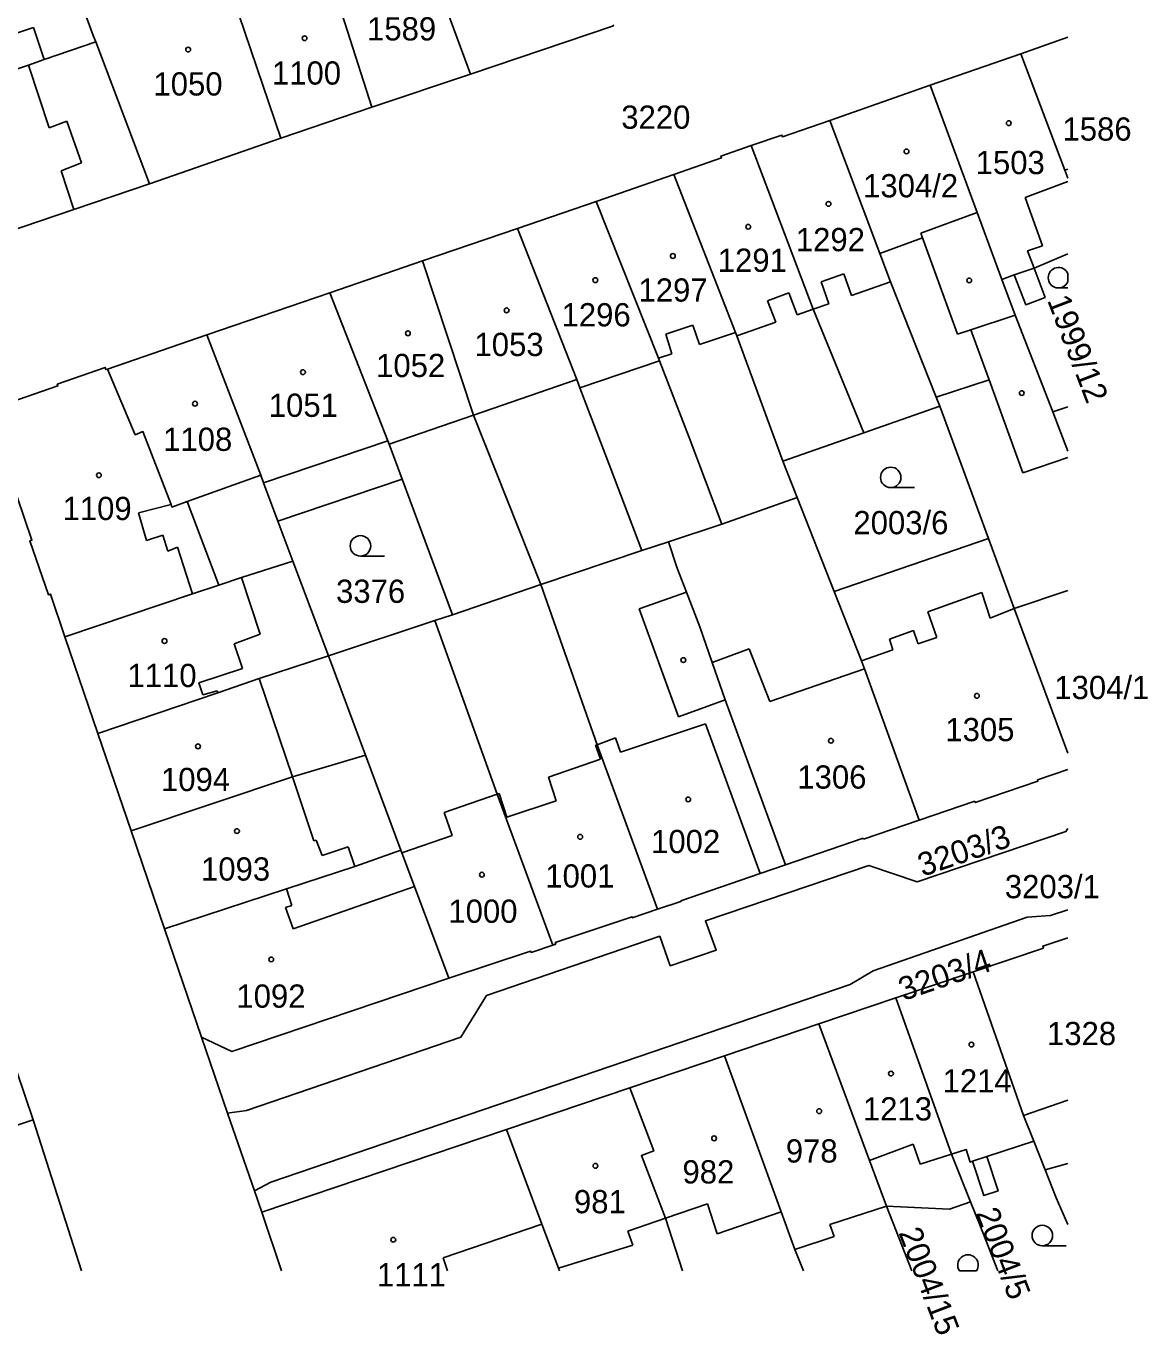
# Model space of a CAD drawing. Extents: x -564952 to -564307, y -1202373 to -1201847.
# Drawn here: x -564390.9 to -564308.8, y -1202366.4 to -1202270.6 of the extents above; entities that cross this region are included whole.
import ezdxf

# ---------------------------------------------------------------- set-up
doc = ezdxf.new("R2010")
doc.units = 0
for name, color, linetype in [('Hranice parcel', 7, 'Continuous'), ('Parcelní čísla', 7, 'Continuous'), ('Vnitřní kresba', 7, 'Continuous'), ('Značky budov', 7, 'Continuous'), ('Značky kultur', 7, 'Continuous')]:
    doc.layers.add(name, color=color, linetype=linetype)

msp = doc.modelspace()

# ---------------------------------------------------------------- linework, layer by layer
at = {"layer": 'Hranice parcel'}
for p, q in [((-564372.23, -1202278.84), (-564376.25, -1202266.98)), ((-564368.89, -1202266.13), (-564365.56, -1202276.57)), ((-564385.77, -1202271.77), (-564385.95, -1202271.31)), ((-564381.83, -1202282.18), (-564385.77, -1202271.77)), ((-564314.648, -1202271.429), (-564318.08, -1202272.65)), ((-564324.71, -1202274.95), (-564318.08, -1202272.65)), ((-564401.02, -1202276.91), (-564390.69, -1202273.49)), ((-564365.56, -1202276.57), (-564358.34, -1202274.15)), ((-564332.06, -1202277.53), (-564324.71, -1202274.95)), ((-564321.28, -1202284.27), (-564324.71, -1202274.95)), ((-564365.56, -1202276.57), (-564372.23, -1202278.84)), ((-564372.23, -1202278.84), (-564381.83, -1202282.18)), ((-564343.48, -1202281.48), (-564349.16, -1202283.47)), ((-564349.16, -1202283.47), (-564354.92, -1202285.44)), ((-564319.47, -1202289.16), (-564321.28, -1202284.27)), ((-564361.86, -1202287.81), (-564354.92, -1202285.44)), ((-564368.65, -1202290.15), (-564361.86, -1202287.81)), ((-564319.47, -1202289.16), (-564318.5, -1202291.78)), ((-564368.65, -1202290.15), (-564377.64, -1202293.21)), ((-564318.5, -1202291.78), (-564315.75, -1202298.85)), ((-564384.92, -1202295.72), (-564377.64, -1202293.21)), ((-564329.57, -1202300.38), (-564324.01, -1202298.43)), ((-564324.01, -1202298.43), (-564324.27, -1202297.77)), ((-564320.44, -1202308.13), (-564324.01, -1202298.43)), ((-564315.75, -1202298.85), (-564314.648, -1202298.478)), ((-564335.5, -1202302.46), (-564329.57, -1202300.38)), ((-564363.34, -1202303.78), (-564364.29, -1202301.23)), ((-564334.45, -1202305.13), (-564335.5, -1202302.46)), ((-564373.49, -1202304.05), (-564372.44, -1202306.86)), ((-564372.44, -1202306.86), (-564363.34, -1202303.78)), ((-564359.66, -1202313.7), (-564363.34, -1202303.78)), ((-564339.97, -1202307.06), (-564334.45, -1202305.13)), ((-564334.45, -1202305.13), (-564331.73, -1202312.01)), ((-564372.44, -1202306.86), (-564371.35, -1202309.77)), ((-564343.86, -1202308.36), (-564339.97, -1202307.06)), ((-564331.73, -1202312.01), (-564320.44, -1202308.13)), ((-564320.44, -1202308.13), (-564318.56, -1202313.24)), ((-564345.81, -1202309.01), (-564353.2, -1202311.48)), ((-564345.81, -1202309.01), (-564343.86, -1202308.36)), ((-564371.35, -1202309.77), (-564375.1, -1202310.97)), ((-564368.75, -1202316.71), (-564371.35, -1202309.77)), ((-564375.1, -1202310.97), (-564376.76, -1202311.53)), ((-564353.2, -1202311.48), (-564359.66, -1202313.7)), ((-564331.73, -1202312.01), (-564329.74, -1202317.06)), ((-564359.66, -1202313.7), (-564360.97, -1202314.13)), ((-564318.56, -1202313.24), (-564314.648, -1202323.815)), ((-564360.97, -1202314.13), (-564368.75, -1202316.71)), ((-564388.02, -1202315.32), (-564385.61, -1202322.39)), ((-564368.75, -1202316.71), (-564373.8, -1202318.37)), ((-564368.75, -1202316.71), (-564366.03, -1202323.98)), ((-564385.61, -1202322.39), (-564383.18, -1202329.52)), ((-564366.03, -1202323.98), (-564363.44, -1202330.93)), ((-564329.6, -1202330.13), (-564325.52, -1202328.74)), ((-564383.18, -1202329.52), (-564380.74, -1202336.69)), ((-564335.31, -1202332), (-564329.62, -1202330.05)), ((-564329.62, -1202330.05), (-564329.6, -1202330.13)), ((-564363.44, -1202330.93), (-564366.81, -1202332.11)), ((-564363.44, -1202330.93), (-564363.37, -1202331.12)), ((-564380.74, -1202336.69), (-564378.04, -1202344.61)), ((-564327.23, -1202341.74), (-564321.57, -1202339.83)), ((-564317.9, -1202350.33), (-564321.57, -1202339.83)), ((-564327.23, -1202341.74), (-564332.87, -1202343.64)), ((-564323.16, -1202353.16), (-564327.23, -1202341.74)), ((-564332.87, -1202343.64), (-564339.77, -1202345.98)), ((-564376.12, -1202350.17), (-564378.04, -1202344.61)), ((-564339.77, -1202345.98), (-564346.68, -1202348.31)), ((-564346.68, -1202348.31), (-564355.71, -1202351.36)), ((-564376.12, -1202350.17), (-564374.16, -1202355.86)), ((-564386.818, -1202361.698), (-564390.35, -1202350.66)), ((-564317.14, -1202352.21), (-564317.9, -1202350.33)), ((-564355.71, -1202351.36), (-564373.62, -1202357.41)), ((-564316.3, -1202354.32), (-564317.14, -1202352.21)), ((-564323.16, -1202353.16), (-564321.77, -1202356.66)), ((-564314.648, -1202353.848), (-564316.3, -1202354.32)), ((-564316.3, -1202354.32), (-564315.49, -1202356.35)), ((-564373.62, -1202357.41), (-564374.16, -1202355.86)), ((-564326.071, -1202361.698), (-564327.92, -1202356.96)), ((-564315.49, -1202356.35), (-564314.648, -1202358.316)), ((-564373.62, -1202357.41), (-564372.175, -1202361.698))]:
    msp.add_line(p, q, dxfattribs=at)
for points in [[(-564358.34, -1202274.15), (-564362.08, -1202264.03), (-564362.9, -1202261.82)], [(-564385.95, -1202271.31), (-564386.4, -1202270.12), (-564386.53, -1202269.77), (-564387.18, -1202268.03)], [(-564358.34, -1202274.15), (-564347.89, -1202270.6), (-564347.92, -1202270.53)], [(-564390.69, -1202273.49), (-564389.53, -1202273.08), (-564385.77, -1202271.77)], [(-564318.08, -1202272.65), (-564314.87, -1202281.17), (-564314.648, -1202281.763)], [(-564332.06, -1202277.53), (-564335.53, -1202278.73), (-564335.57, -1202278.6), (-564337.81, -1202279.37)], [(-564324.27, -1202297.77), (-564327.62, -1202289.35), (-564328.4, -1202287.27), (-564332.06, -1202277.53)], [(-564337.81, -1202279.37), (-564340.03, -1202280.14), (-564339.99, -1202280.27), (-564343.48, -1202281.48)], [(-564329.57, -1202300.38), (-564333.29, -1202291.34), (-564337.81, -1202279.37)], [(-564397.45, -1202287.47), (-564387.37, -1202284.06), (-564381.83, -1202282.18)], [(-564343.48, -1202281.48), (-564338.97, -1202293.04), (-564338.87, -1202293.3), (-564335.5, -1202302.46)], [(-564339.97, -1202307.06), (-564342.36, -1202300.74), (-564344.53, -1202295.11), (-564344.6, -1202294.93), (-564349.16, -1202283.47)], [(-564354.92, -1202285.44), (-564350.58, -1202296.49), (-564350.35, -1202297.09), (-564348.07, -1202303.02), (-564345.81, -1202309.01)], [(-564353.2, -1202311.48), (-564358.13, -1202299.1), (-564361.86, -1202287.81)], [(-564314.648, -1202287.303), (-564317.11, -1202288.33), (-564316.3, -1202290.48)], [(-564316.3, -1202290.48), (-564317.73, -1202291.02), (-564318.56, -1202288.82), (-564319.47, -1202289.16)], [(-564364.29, -1202301.23), (-564364.39, -1202300.97), (-564368.65, -1202290.15)], [(-564318.5, -1202291.78), (-564321.74, -1202292.86), (-564320.41, -1202296.51), (-564324.27, -1202297.77)], [(-564377.64, -1202293.21), (-564373.7, -1202303.49), (-564373.49, -1202304.05)], [(-564393.68, -1202298.73), (-564388.54, -1202296.96), (-564388.58, -1202296.83), (-564385.09, -1202295.6), (-564385.03, -1202295.76), (-564384.92, -1202295.72)], [(-564384.92, -1202295.72), (-564382.88, -1202300.53), (-564382.32, -1202300.3), (-564380.25, -1202305.63), (-564380.19, -1202305.82), (-564379.07, -1202305.42), (-564376.76, -1202311.53)], [(-564388.02, -1202315.32), (-564389.09, -1202312.19), (-564389.23, -1202312.24), (-564390.58, -1202308.29), (-564390.44, -1202308.24), (-564393.68, -1202298.73)], [(-564315.75, -1202298.85), (-564314.648, -1202301.72)], [(-564341.56, -1202314.59), (-564342.54, -1202312.05), (-564343.22, -1202310.3), (-564343.86, -1202308.36)], [(-564376.76, -1202311.53), (-564378.7, -1202312.18), (-564388.02, -1202315.32)], [(-564344.67, -1202335.25), (-564349.09, -1202323.21), (-564353.2, -1202311.48)], [(-564352.33, -1202337.87), (-564356.4, -1202326.83), (-564360.97, -1202314.13)], [(-564335.31, -1202332), (-564339.71, -1202319.93), (-564340.66, -1202317.19), (-564341.56, -1202314.59)], [(-564329.74, -1202317.06), (-564329.53, -1202317.65), (-564325.52, -1202328.74)], [(-564373.8, -1202318.37), (-564376.83, -1202319.4), (-564385.61, -1202322.39)], [(-564366.03, -1202323.98), (-564371.38, -1202325.57), (-564383.18, -1202329.52)], [(-564325.52, -1202328.74), (-564321.45, -1202327.35), (-564321.42, -1202327.44), (-564316.83, -1202325.88), (-564316.86, -1202325.78), (-564314.648, -1202325.026)], [(-564314.648, -1202329.344), (-564314.78, -1202329.56), (-564325.67, -1202333.25), (-564329.21, -1202332.05), (-564341.16, -1202336.1), (-564340.37, -1202338.24), (-564343.73, -1202339.38), (-564344.5, -1202337.22), (-564357.19, -1202341.56), (-564359.05, -1202344.6), (-564374.74, -1202349.96), (-564376.12, -1202350.17)], [(-564363.37, -1202331.12), (-564362.45, -1202333.57), (-564359.93, -1202340.28)], [(-564366.81, -1202332.11), (-564371.82, -1202333.76), (-564380.74, -1202336.69)], [(-564342.97, -1202334.62), (-564337.16, -1202332.63), (-564335.31, -1202332)], [(-564344.67, -1202335.25), (-564342.95, -1202334.69), (-564342.97, -1202334.62)], [(-564374.16, -1202355.86), (-564372.96, -1202355.22), (-564330.58, -1202340.76), (-564328.9, -1202339.76), (-564317.61, -1202335.83), (-564315.91, -1202335.71), (-564314.648, -1202335.286)], [(-564352.33, -1202337.87), (-564352.11, -1202337.79), (-564352.15, -1202337.68), (-564346.53, -1202335.8), (-564346.51, -1202335.87), (-564344.67, -1202335.25)], [(-564390.35, -1202350.66), (-564392.14, -1202345.32), (-564392.29, -1202345.37), (-564395.36, -1202336.41)], [(-564359.93, -1202340.28), (-564353.95, -1202338.32), (-564353.92, -1202338.41), (-564352.33, -1202337.87)], [(-564321.57, -1202339.83), (-564316.43, -1202338.09), (-564316.48, -1202337.95), (-564314.648, -1202337.328)], [(-564378.04, -1202344.61), (-564375.81, -1202345.65), (-564359.93, -1202340.28)], [(-564327.92, -1202356.96), (-564329.16, -1202353.63), (-564332.87, -1202343.64)], [(-564339.77, -1202345.98), (-564335.62, -1202357.39), (-564334.61, -1202360.15)], [(-564342.842, -1202361.698), (-564344.09, -1202357.85), (-564345.84, -1202353.27), (-564344.94, -1202352.93), (-564346.68, -1202348.31)], [(-564390.35, -1202350.66), (-564395.73, -1202352.45), (-564395.78, -1202352.31), (-564402.54, -1202354.66), (-564406.74, -1202356.11)], [(-564355.71, -1202351.36), (-564353.14, -1202358.28), (-564351.92, -1202361.5), (-564351.846, -1202361.698)], [(-564317.14, -1202352.21), (-564320.58, -1202353.34), (-564319.75, -1202355.86), (-564320.79, -1202356.2), (-564321.62, -1202353.68), (-564321.8, -1202353.74), (-564322.09, -1202352.82), (-564323.16, -1202353.16)], [(-564327.92, -1202356.96), (-564323.31, -1202357.18), (-564321.77, -1202356.66)], [(-564321.77, -1202356.66), (-564321.08, -1202358.34), (-564319.76, -1202361.698)], [(-564334.61, -1202360.15), (-564333.994, -1202361.698)]]:
    msp.add_lwpolyline(points, dxfattribs=at)
at = {"layer": 'Vnitřní kresba'}
for p, q in [((-564390.31, -1202270.74), (-564393.18, -1202271.69)), ((-564389.53, -1202273.08), (-564390.31, -1202270.74)), ((-564389.18, -1202278.07), (-564390.69, -1202273.49)), ((-564387.89, -1202277.58), (-564389.18, -1202278.07)), ((-564386.81, -1202280.64), (-564387.89, -1202277.58)), ((-564388.31, -1202281.21), (-564386.81, -1202280.64)), ((-564387.37, -1202284.06), (-564388.31, -1202281.21)), ((-564314.87, -1202281.17), (-564314.648, -1202281.087)), ((-564317.77, -1202283.18), (-564314.648, -1202281.999)), ((-564316.49, -1202286.71), (-564317.77, -1202283.18)), ((-564325.41, -1202285.79), (-564321.28, -1202284.27)), ((-564328.4, -1202287.27), (-564325.29, -1202286.12)), ((-564325.29, -1202286.12), (-564325.41, -1202285.79)), ((-564322.72, -1202293.18), (-564325.29, -1202286.12)), ((-564317.59, -1202287.07), (-564316.49, -1202286.71)), ((-564317.11, -1202288.33), (-564317.59, -1202287.07)), ((-564332.7, -1202289.33), (-564331.04, -1202288.75)), ((-564331.04, -1202288.75), (-564330.48, -1202290.35)), ((-564318.56, -1202288.82), (-564317.11, -1202288.33)), ((-564332.14, -1202290.94), (-564332.7, -1202289.33)), ((-564330.48, -1202290.35), (-564327.62, -1202289.35)), ((-564336.61, -1202290.74), (-564335.05, -1202290.15)), ((-564336.02, -1202292.3), (-564336.61, -1202290.74)), ((-564335.05, -1202290.15), (-564334.46, -1202291.75)), ((-564333.29, -1202291.34), (-564332.14, -1202290.94)), ((-564334.46, -1202291.75), (-564333.29, -1202291.34)), ((-564344.06, -1202293.18), (-564342.08, -1202292.51)), ((-564342.08, -1202292.51), (-564341.6, -1202293.92)), ((-564338.87, -1202293.3), (-564336.02, -1202292.3)), ((-564322.72, -1202293.18), (-564321.74, -1202292.86)), ((-564343.61, -1202294.6), (-564344.06, -1202293.18)), ((-564341.6, -1202293.92), (-564338.97, -1202293.04)), ((-564344.6, -1202294.93), (-564343.61, -1202294.6)), ((-564350.35, -1202297.09), (-564344.53, -1202295.11)), ((-564350.58, -1202296.49), (-564358.13, -1202299.1)), ((-564317.94, -1202303.31), (-564320.41, -1202296.51)), ((-564358.13, -1202299.1), (-564364.29, -1202301.23)), ((-564364.39, -1202300.97), (-564373.49, -1202304.05)), ((-564314.648, -1202302.184), (-564317.94, -1202303.31)), ((-564373.7, -1202303.49), (-564379.07, -1202305.42)), ((-564382.63, -1202306.23), (-564380.25, -1202305.63)), ((-564382.06, -1202308.26), (-564382.63, -1202306.23)), ((-564380.85, -1202307.88), (-564382.06, -1202308.26)), ((-564380.5, -1202309.05), (-564380.85, -1202307.88)), ((-564379.78, -1202308.76), (-564380.5, -1202309.05)), ((-564378.7, -1202312.18), (-564379.78, -1202308.76)), ((-564375.1, -1202310.97), (-564373.73, -1202315.12)), ((-564318.56, -1202313.24), (-564314.648, -1202311.917)), ((-564346.02, -1202313.26), (-564342.54, -1202312.05)), ((-564320.94, -1202312.07), (-564324.9, -1202313.48)), ((-564320.34, -1202313.94), (-564320.94, -1202312.07)), ((-564343.12, -1202321.18), (-564346.02, -1202313.26)), ((-564324.24, -1202315.37), (-564324.9, -1202313.48)), ((-564318.56, -1202313.24), (-564320.34, -1202313.94)), ((-564325.93, -1202314.86), (-564327.7, -1202315.48)), ((-564325.68, -1202315.64), (-564325.93, -1202314.86)), ((-564373.73, -1202315.12), (-564375.65, -1202315.83)), ((-564375.65, -1202315.83), (-564375.03, -1202317.63)), ((-564327.46, -1202316.26), (-564327.7, -1202315.48)), ((-564325.68, -1202315.64), (-564325.62, -1202315.83)), ((-564325.62, -1202315.83), (-564324.24, -1202315.37)), ((-564340.66, -1202317.19), (-564337.96, -1202316.2)), ((-564336.46, -1202320.05), (-564337.96, -1202316.2)), ((-564329.74, -1202317.06), (-564327.46, -1202316.26)), ((-564375.03, -1202317.63), (-564378.23, -1202318.69)), ((-564329.53, -1202317.65), (-564336.46, -1202320.05)), ((-564377.94, -1202319.57), (-564378.23, -1202318.69)), ((-564371.38, -1202325.57), (-564373.8, -1202318.37)), ((-564377.94, -1202319.57), (-564376.88, -1202319.26)), ((-564376.83, -1202319.4), (-564376.88, -1202319.26)), ((-564343.12, -1202321.18), (-564339.71, -1202319.93)), ((-564341.15, -1202321.67), (-564347.38, -1202323.75)), ((-564337.16, -1202332.63), (-564341.15, -1202321.67)), ((-564349.09, -1202323.21), (-564349.21, -1202323.25)), ((-564348.83, -1202324.27), (-564349.21, -1202323.25)), ((-564347.74, -1202322.71), (-564349.09, -1202323.21)), ((-564347.38, -1202323.75), (-564347.74, -1202322.71)), ((-564352.65, -1202325.58), (-564348.83, -1202324.27)), ((-564369.82, -1202330.24), (-564371.38, -1202325.57)), ((-564352.65, -1202325.58), (-564352.07, -1202327.32)), ((-564360.27, -1202328.16), (-564356.4, -1202326.83)), ((-564356.4, -1202326.83), (-564356.26, -1202326.78)), ((-564355.68, -1202328.52), (-564356.26, -1202326.78)), ((-564352.07, -1202327.32), (-564355.68, -1202328.52)), ((-564360.27, -1202328.16), (-564359.68, -1202329.85)), ((-564369.64, -1202330.19), (-564369.82, -1202330.24)), ((-564369.21, -1202331.32), (-564369.64, -1202330.19)), ((-564359.68, -1202329.85), (-564363.37, -1202331.12)), ((-564367.31, -1202330.69), (-564369.21, -1202331.32)), ((-564366.81, -1202332.11), (-564367.31, -1202330.69)), ((-564371.41, -1202334.97), (-564371.82, -1202333.76)), ((-564371.33, -1202336.67), (-564362.45, -1202333.57)), ((-564371.89, -1202335.13), (-564371.41, -1202334.97)), ((-564371.33, -1202336.67), (-564371.89, -1202335.13)), ((-564314.648, -1202349.216), (-564317.9, -1202350.33)), ((-564325.97, -1202352.43), (-564329.16, -1202353.63)), ((-564325.45, -1202353.9), (-564325.97, -1202352.43)), ((-564323.16, -1202353.16), (-564325.45, -1202353.9)), ((-564320.58, -1202353.34), (-564321.62, -1202353.68)), ((-564341.02, -1202356.8), (-564344.09, -1202357.85)), ((-564340.31, -1202359), (-564341.02, -1202356.8)), ((-564327.92, -1202356.96), (-564332.05, -1202358.31)), ((-564344.09, -1202357.85), (-564346.84, -1202358.79)), ((-564335.62, -1202357.39), (-564340.31, -1202359)), ((-564353.14, -1202358.28), (-564360.35, -1202360.74)), ((-564346.84, -1202358.79), (-564346.47, -1202359.83)), ((-564332.05, -1202358.31), (-564331.74, -1202359.18)), ((-564346.47, -1202359.83), (-564351.92, -1202361.5)), ((-564331.74, -1202359.18), (-564334.61, -1202360.15)), ((-564360.35, -1202360.74), (-564360.032, -1202361.698))]:
    msp.add_line(p, q, dxfattribs=at)
at = {"layer": 'Značky budov'}
for centre in [(-564370.487, -1202271.519), (-564379.007, -1202272.349), (-564318.967, -1202277.729), (-564326.447, -1202279.799), (-564332.157, -1202283.639), (-564338.027, -1202285.309), (-564343.547, -1202287.449), (-564349.217, -1202289.219), (-564321.857, -1202289.239), (-564355.707, -1202291.429), (-564362.927, -1202293.109), (-564370.607, -1202295.949), (-564318.017, -1202297.479), (-564378.507, -1202298.259), (-564385.537, -1202303.489), (-564380.737, -1202315.619), (-564342.777, -1202317.019), (-564321.297, -1202319.629), (-564378.287, -1202323.329), (-564331.977, -1202322.919), (-564342.417, -1202327.209), (-564375.437, -1202329.529), (-564350.327, -1202329.949), (-564357.517, -1202332.719), (-564372.927, -1202338.919), (-564321.697, -1202345.149), (-564327.587, -1202347.269), (-564332.837, -1202350.019), (-564340.527, -1202352.009), (-564349.207, -1202354.019), (-564363.997, -1202359.429)]:
    msp.add_circle(centre, 0.175, dxfattribs=at)
at = {"layer": 'Značky kultur'}
for p, q in [((-564314.648, -1202289.345), (-564314.648, -1202288.735)), ((-564315.333, -1202289.79), (-564314.648, -1202289.79)), ((-564327.603, -1202304.4), (-564325.853, -1202304.4)), ((-564366.403, -1202309.41), (-564364.653, -1202309.41)), ((-564316.513, -1202359.87), (-564314.763, -1202359.87)), ((-564322.575, -1202361.698), (-564321.331, -1202361.698))]:
    msp.add_line(p, q, dxfattribs=at)
for centre in [(-564327.603, -1202303.65), (-564366.403, -1202308.66), (-564316.513, -1202359.12)]:
    msp.add_circle(centre, 0.75, dxfattribs=at)
for centre, start, end in [((-564315.333, -1202289.04), 23.991, 336.009), ((-564321.953, -1202361.28), 326.06534, 213.93466)]:
    msp.add_arc(centre, 0.75, start, end, dxfattribs=at)

# ---------------------------------------------------------------- texts
at = {"layer": 'Parcelní čísla'}
for s, p in [('1589', (-564365.917, -1202271.68)), ('1100', (-564372.877, -1202274.91)), ('1050', (-564381.547, -1202275.71)), ('3220', (-564347.317, -1202278.14)), ('1586', (-564315.037, -1202279.01)), ('1503', (-564321.387, -1202281.46)), ('1304/2', (-564329.625, -1202283.16)), ('1292', (-564334.547, -1202287.1)), ('1291', (-564340.257, -1202288.61)), ('1297', (-564346.057, -1202290.79)), ('1296', (-564351.687, -1202292.6)), ('1053', (-564358.057, -1202294.77)), ('1052', (-564365.257, -1202296.31)), ('1051', (-564373.107, -1202299.22)), ('1108', (-564380.837, -1202301.71)), ('1109', (-564388.197, -1202306.77)), ('2003/6', (-564330.335, -1202307.81)), ('3376', (-564368.187, -1202312.83)), ('1110', (-564383.447, -1202318.99)), ('1304/1', (-564315.635, -1202319.87)), ('1305', (-564323.607, -1202322.95)), ('1094', (-564380.997, -1202326.6)), ('1306', (-564334.437, -1202326.42)), ('1002', (-564345.137, -1202331.14)), ('1093', (-564378.067, -1202333.15)), ('1001', (-564352.877, -1202333.66)), ('3203/1', (-564319.255, -1202334.44)), ('1000', (-564359.967, -1202336.24)), ('1092', (-564375.477, -1202342.45)), ('1328', (-564316.17, -1202345.19)), ('1214', (-564323.81, -1202348.65)), ('1213', (-564329.64, -1202350.7)), ('978', (-564335.28, -1202353.78)), ('982', (-564342.84, -1202355.31)), ('981', (-564350.78, -1202357.49)), ('1111', (-564365.2, -1202362.84))]:
    msp.add_text(s, height=1.7, dxfattribs=at).set_placement(p)
for s, rotation, p in [('1999/12', 291, (-564316.178, -1202290.681)), ('3203/3', 19, (-564325.268, -1202332.879)), ('3203/4', 19, (-564326.678, -1202341.969)), ('2004/5', 291, (-564321.393, -1202357.464)), ('2004/15', 291, (-564327.053, -1202358.904))]:
    msp.add_text(s, height=1.7, rotation=rotation, dxfattribs=at).set_placement(p)

doc.saveas('drawing.dxf')
